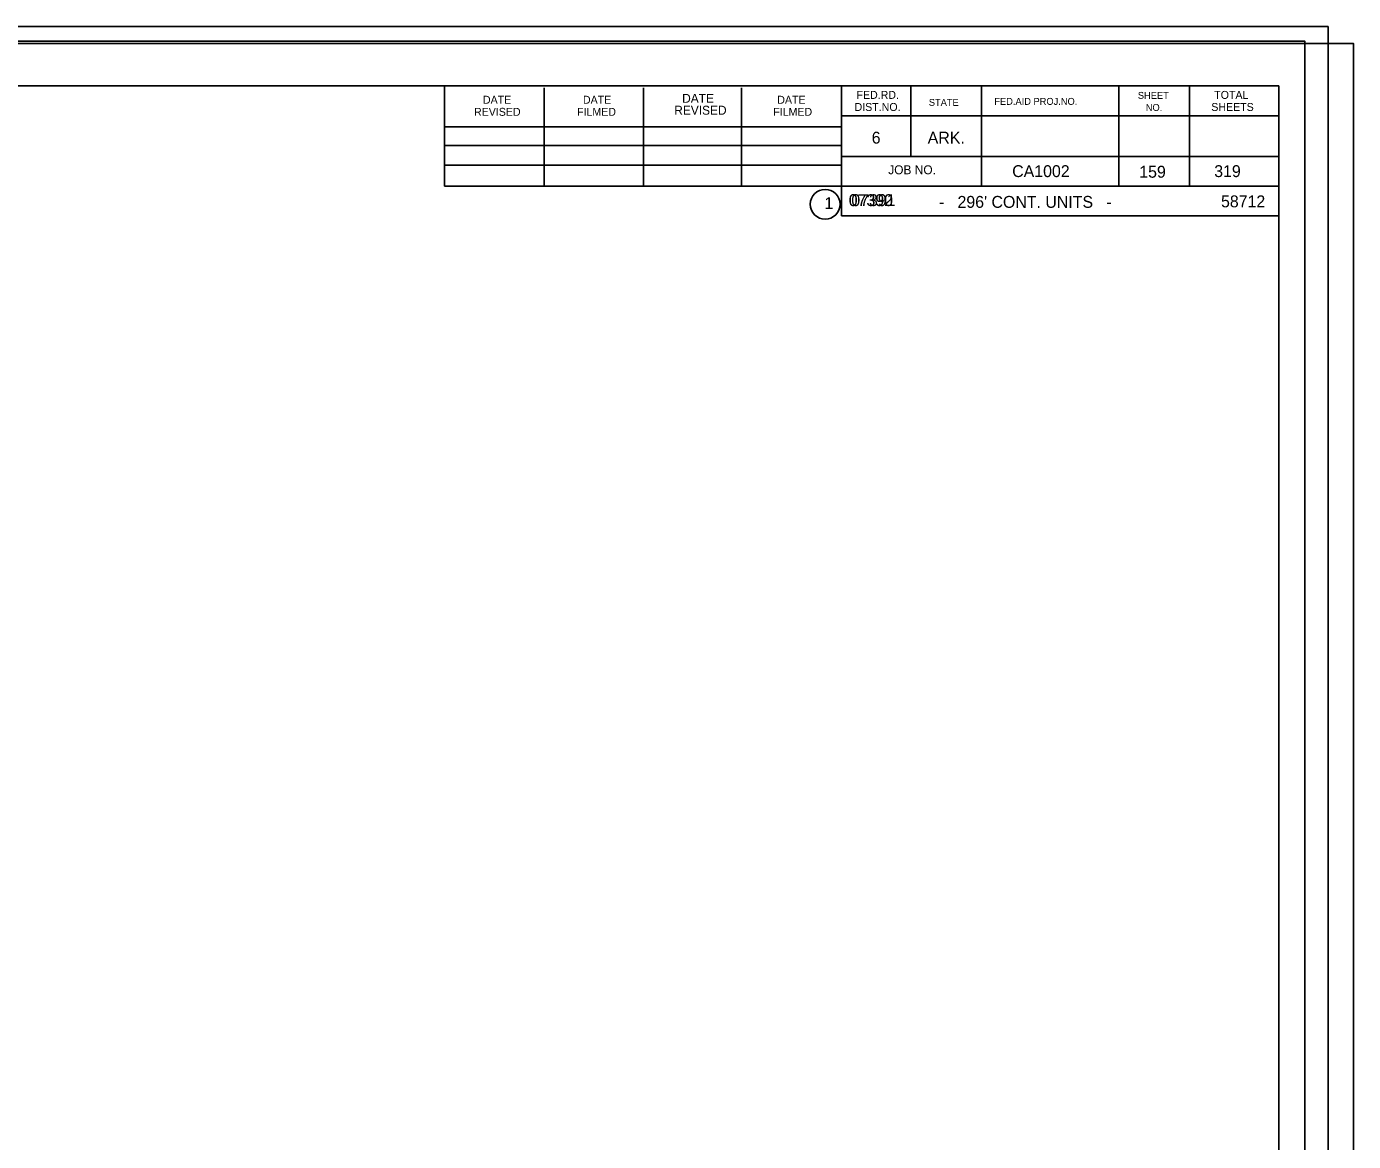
# Model space of a CAD drawing. Extents: x -725.7 to -683.7, y 85.6 to 107.6.
# Drawn here: x -704.28 to -691.19, y 96.61 to 107.6 of the extents above; entities that cross this region are included whole.
import ezdxf

# ---------------------------------------------------------------- set-up
doc = ezdxf.new("R2010")
doc.units = 0
for name, color, linetype in [('border', 7, 'Continuous'), ('Border 2660-Hwy18 - Level 62', 7, 'Continuous'), ('Border 2660-Hwy18 - Level 63', 7, 'Continuous'), ('Border 2660-Hwy18 - Text', 7, 'Continuous'), ('Bridge No BLFR', 7, 'Continuous'), ('Bridge No BLO', 7, 'Continuous'), ('Bridge No Ditch 81', 7, 'Continuous'), ('Level 62 PDF', 7, 'Continuous'), ('Text', 7, 'Continuous'), ('Title Text', 7, 'Continuous')]:
    doc.layers.add(name, color=color, linetype=linetype)

msp = doc.modelspace()

# ---------------------------------------------------------------- linework, layer by layer
at = {"layer": 'border'}
for p, q in [((-723.942, 107.01), (-691.93, 107.01)), ((-700.156, 106.022), (-700.156, 107.01)), ((-699.171, 106.022), (-699.171, 106.991)), ((-698.194, 106.022), (-698.194, 106.991)), ((-697.227, 106.022), (-697.227, 106.991)), ((-696.241, 107.01), (-696.241, 105.731)), ((-695.557, 107.01), (-695.557, 106.316)), ((-694.862, 107.01), (-694.862, 106.022)), ((-693.505, 107.01), (-693.505, 106.022)), ((-692.81, 107.01), (-692.81, 106.022)), ((-691.93, 86.465), (-691.93, 107.01)), ((-691.93, 106.716), (-696.241, 106.716)), ((-691.93, 106.718), (-691.93, 106.718)), ((-700.156, 106.608), (-696.241, 106.608)), ((-700.156, 106.422), (-696.241, 106.422)), ((-691.93, 106.316), (-696.241, 106.316)), ((-695.944, 106.316), (-691.93, 106.316)), ((-700.156, 106.022), (-700.156, 106.229)), ((-700.156, 106.229), (-696.241, 106.229)), ((-691.93, 106.022), (-700.156, 106.022)), ((-696.241, 105.731), (-691.93, 105.731))]:
    msp.add_line(p, q, dxfattribs=at)
msp.add_circle((-696.402, 105.844), 0.147, dxfattribs=at)
at = {"layer": 'Border 2660-Hwy18 - Level 62'}
msp.add_lwpolyline([(-725.562, 107.596), (-691.443, 107.596), (-691.443, 85.786), (-725.562, 85.786)], close=True, dxfattribs=at)
at = {"layer": 'Border 2660-Hwy18 - Level 63'}
msp.add_lwpolyline([(-725.673, 107.453), (-691.673, 107.453), (-691.673, 86.083), (-725.673, 86.083)], close=True, dxfattribs=at)
at = {"layer": 'Level 62 PDF'}
msp.add_lwpolyline([(-725.312, 107.429), (-691.193, 107.429), (-691.193, 85.62), (-725.312, 85.62)], close=True, dxfattribs=at)

# ---------------------------------------------------------------- texts
at = {"layer": 'Border 2660-Hwy18 - Text'}
for s, height, p in [('DATE', 0.0782, (-699.776, 106.835)), ('DATE', 0.0782, (-698.79, 106.835)), ('DATE', 0.0879, (-697.812, 106.844)), ('DATE', 0.0782, (-696.874, 106.835)), ('FED.RD.', 0.0782, (-696.093, 106.883)), ('FED.AID PROJ.NO.', 0.06839, (-694.734, 106.824)), ('SHEET', 0.0684, (-693.319, 106.883)), ('TOTAL', 0.0782, (-692.566, 106.883)), ('REVISED', 0.0782, (-699.864, 106.716)), ('FILMED', 0.0782, (-698.848, 106.716)), ('REVISED', 0.0879, (-697.89, 106.727)), ('FILMED', 0.0782, (-696.914, 106.716)), ('DIST.NO.', 0.0782, (-696.112, 106.764)), ('STATE', 0.0684, (-695.38, 106.814)), ('NO.', 0.0684, (-693.241, 106.764)), ('SHEETS', 0.0782, (-692.595, 106.764)), ('6', 0.117, (-695.943, 106.442)), ('ARK.', 0.1172, (-695.391, 106.442)), ('JOB NO.', 0.0879, (-695.78, 106.14)), ('CA1002', 0.1172, (-694.558, 106.112)), ('319', 0.1172, (-692.566, 106.112)), ('1', 0.117, (-696.409, 105.797))]:
    msp.add_text(s, height=height, dxfattribs=at).set_placement(p)
at = {"layer": 'Bridge No BLFR'}
msp.add_text('07392', height=0.1172, dxfattribs=at).set_placement((-696.17, 105.826))
at = {"layer": 'Bridge No BLO'}
msp.add_text('07391', height=0.1172, dxfattribs=at).set_placement((-696.144, 105.826))
at = {"layer": 'Bridge No Ditch 81'}
msp.add_text('07390', height=0.1172, dxfattribs=at).set_placement((-696.169, 105.826))
at = {"layer": 'Text'}
msp.add_text('159', height=0.1172, dxfattribs=at).set_placement((-693.305, 106.106))
at = {"layer": 'Title Text'}
for s, height, p in [("-   296' CONT. UNITS   -", 0.11722, (-695.28, 105.809)), ('58712', 0.1172, (-692.499, 105.814))]:
    msp.add_text(s, height=height, dxfattribs=at).set_placement(p)

doc.saveas('drawing.dxf')
